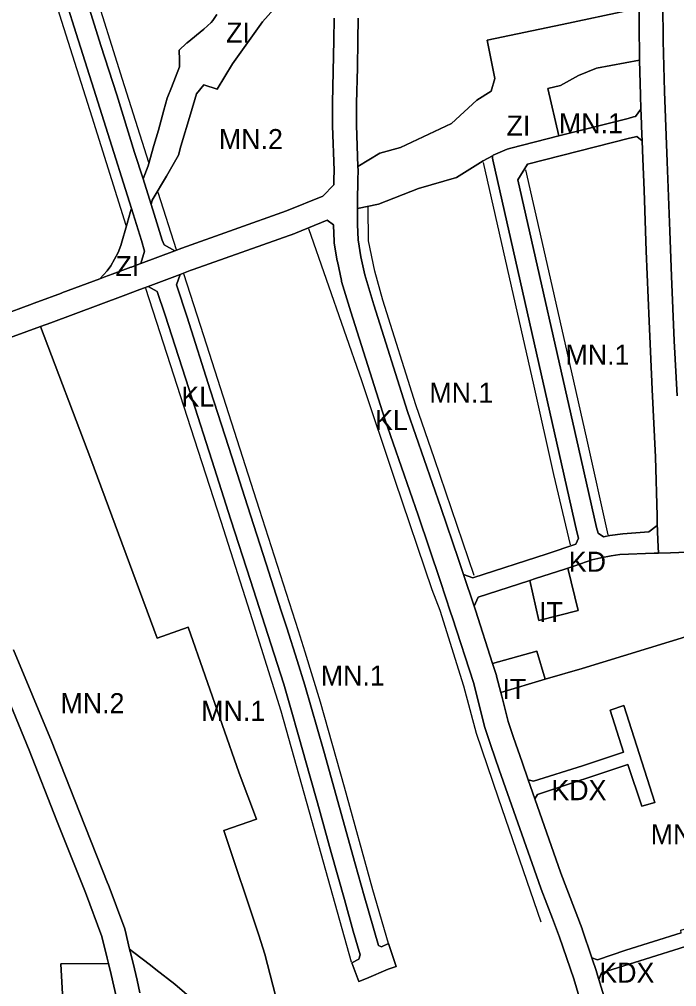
# Model space of a CAD drawing. Extents: x 7431767 to 7433133, y 5549450 to 5550702.
# Drawn here: x 7432434.9 to 7432763, y 5549892.8 to 5550375.6 of the extents above; entities that cross this region are included whole.
import ezdxf

# ---------------------------------------------------------------- set-up
doc = ezdxf.new("R2010")
doc.units = 0
for name, color, linetype in [('linie_rozgraniczajace', 7, 'Continuous'), ('nieprzekraczalne_linie_zabudowy', 7, 'Continuous'), ('oznaczenia_przeznaczen', 7, 'Continuous')]:
    doc.layers.add(name, color=color, linetype=linetype)

msp = doc.modelspace()

# ---------------------------------------------------------------- linework, layer by layer
at = {"layer": 'linie_rozgraniczajace'}
for points in [[(7432763.25, 5550187.7), (7432761.8, 5550215.11), (7432760.42, 5550247.43), (7432759.57, 5550269.96), (7432758.24, 5550304.4), (7432757.03, 5550339.63), (7432756.31, 5550364.95), (7432756.15, 5550383.55), (7432755.03, 5550391.98), (7432753.71, 5550401.33), (7432750.6, 5550417.95), (7432748.59, 5550428.19), (7432745.65, 5550438.8), (7432738.12, 5550465.56), (7432733.72, 5550481.6), (7432731.08, 5550491.16), (7432728.74, 5550502.72), (7432725.9, 5550519.48), (7432722.27, 5550540.38), (7432716.74, 5550573.19), (7432713.32, 5550592.83), (7432717.85, 5550589.96), (7432748.22, 5550570.66), (7432769.72, 5550550.02)], [(7432453.63, 5550399.36), (7432463.29, 5550368.48), (7432472.11, 5550340.78), (7432479.98, 5550315.54), (7432488.91, 5550287.48), (7432490.89, 5550281.13), (7432490.29, 5550279.68), (7432488.78, 5550273.77), (7432485.47, 5550262.65), (7432484.27, 5550259.27), (7432480.54, 5550252.54), (7432478.7, 5550250.05), (7432474.98, 5550246.08), (7432456.07, 5550239.03), (7432455.88, 5550238.96), (7432444.11, 5550234.59), (7432441.77, 5550233.72), (7432441.37, 5550233.57), (7432425.1, 5550227.62)], [(7432467.34, 5550388.9), (7432475.63, 5550362.6), (7432483.49, 5550337.84), (7432492.44, 5550309.07), (7432496.63, 5550295.93), (7432500.68, 5550283.19), (7432502.22, 5550278.43), (7432506.26, 5550265.31), (7432507.13, 5550263.14), (7432512.5, 5550260.14), (7432495.47, 5550253.73), (7432497.44, 5550259.83), (7432495.79, 5550265.14), (7432490.89, 5550281.13), (7432488.91, 5550287.48), (7432479.98, 5550315.54), (7432472.11, 5550340.78), (7432463.29, 5550368.48), (7432453.63, 5550399.36)], [(7432533.46, 5550377.98), (7432531.55, 5550375), (7432530.58, 5550374.07), (7432526.97, 5550370.61), (7432518.61, 5550363.93), (7432518.31, 5550363.66), (7432514.73, 5550360.21), (7432514.83, 5550355.38), (7432514.78, 5550351.93), (7432510.83, 5550341.51), (7432508.67, 5550336.19), (7432507.06, 5550330.24), (7432504.31, 5550320.29), (7432502.08, 5550312.68), (7432499.12, 5550302.54), (7432496.63, 5550295.93), (7432492.44, 5550309.07), (7432483.49, 5550337.84), (7432475.63, 5550362.6), (7432467.34, 5550388.9)], [(7432566.17, 5550385.73), (7432556.25, 5550374.31), (7432541.21, 5550353.36), (7432533.69, 5550340.77), (7432527.03, 5550342.86), (7432523.4, 5550338.38), (7432520.31, 5550328.19), (7432515.52, 5550312.27), (7432514.32, 5550307.76), (7432508.37, 5550297.36), (7432501.16, 5550285.34), (7432500.68, 5550283.19), (7432496.63, 5550295.93), (7432499.12, 5550302.54), (7432502.08, 5550312.68), (7432504.31, 5550320.29), (7432507.06, 5550330.24), (7432508.67, 5550336.19), (7432510.83, 5550341.51), (7432514.78, 5550351.93), (7432514.83, 5550355.38), (7432514.73, 5550360.21), (7432518.31, 5550363.66), (7432518.61, 5550363.93), (7432526.97, 5550370.61), (7432530.58, 5550374.07), (7432531.55, 5550375), (7432533.46, 5550377.98)], [(7432592.01, 5550376.26), (7432591.93, 5550365.18), (7432591.29, 5550333.96), (7432591.22, 5550322.64), (7432591.19, 5550322.5), (7432591.97, 5550300.15), (7432591.87, 5550295.66), (7432591.85, 5550293.05), (7432586.36, 5550287.41), (7432568.33, 5550280), (7432516.05, 5550261.47), (7432512.5, 5550260.14), (7432507.13, 5550263.14), (7432506.26, 5550265.31), (7432502.22, 5550278.43), (7432500.68, 5550283.19), (7432501.16, 5550285.34), (7432508.37, 5550297.36), (7432514.32, 5550307.76), (7432515.52, 5550312.27), (7432520.31, 5550328.19), (7432523.4, 5550338.38), (7432527.03, 5550342.86), (7432533.69, 5550340.77), (7432541.21, 5550353.36), (7432556.25, 5550374.31), (7432566.17, 5550385.73)], [(7432756.15, 5550383.55), (7432756.31, 5550364.95), (7432757.03, 5550339.63), (7432758.24, 5550304.4), (7432759.57, 5550269.96), (7432760.42, 5550247.43), (7432761.8, 5550215.11), (7432763.25, 5550187.7)], [(7432740.24, 5550380.4), (7432705.79, 5550373.09), (7432668.36, 5550365.21), (7432672.26, 5550346.13), (7432670.49, 5550339.82), (7432663.35, 5550335.32), (7432650.57, 5550323.57), (7432625.16, 5550311.62), (7432614.82, 5550308.86), (7432603.9, 5550302.18), (7432603.19, 5550322.78), (7432603.27, 5550333.83), (7432603.62, 5550351.4), (7432603.91, 5550365.04), (7432604.02, 5550376.25)], [(7432744.33, 5550381.26), (7432744.33, 5550372.08), (7432744.48, 5550356.8), (7432744.51, 5550355.21), (7432722.94, 5550351.17), (7432713.99, 5550347.49), (7432705.02, 5550342.58), (7432698.74, 5550341.09), (7432704.26, 5550317.38), (7432680.21, 5550311.26), (7432678.45, 5550310.88), (7432671.38, 5550307.73), (7432671.01, 5550307.53), (7432666.39, 5550304.98), (7432653.16, 5550296.61), (7432634.12, 5550291.18), (7432614.11, 5550283.37), (7432603.75, 5550281.15), (7432603.77, 5550284.42), (7432603.7, 5550284.69), (7432603.89, 5550295.47), (7432603.95, 5550300.08), (7432603.92, 5550300.23), (7432603.97, 5550300.4), (7432603.9, 5550302.18), (7432614.82, 5550308.86), (7432625.16, 5550311.62), (7432650.57, 5550323.57), (7432663.35, 5550335.32), (7432670.49, 5550339.82), (7432672.26, 5550346.13), (7432668.36, 5550365.21), (7432705.79, 5550373.09), (7432740.24, 5550380.4)], [(7432789.4, 5550110.52), (7432759.93, 5550109.32), (7432753.99, 5550109.16), (7432753.6, 5550115.69), (7432753.42, 5550120.18), (7432753.38, 5550121.22), (7432753.37, 5550122.95), (7432753.34, 5550124.42), (7432753.3, 5550127.79), (7432752.43, 5550157.07), (7432750.87, 5550190.84), (7432749.29, 5550225), (7432747.82, 5550259.82), (7432746.77, 5550290.3), (7432746.07, 5550305.96), (7432745.77, 5550314.94), (7432745.76, 5550315.29), (7432745.66, 5550317.72), (7432745.31, 5550327.88), (7432745.22, 5550330.7), (7432744.97, 5550337.75), (7432744.51, 5550355.21), (7432744.48, 5550356.8), (7432744.33, 5550372.08), (7432744.33, 5550381.26)], [(7432425.1, 5550227.62), (7432441.37, 5550233.57), (7432441.77, 5550233.72), (7432444.11, 5550234.59), (7432455.88, 5550238.96), (7432456.07, 5550239.03), (7432474.98, 5550246.08), (7432477.54, 5550247.03), (7432481.27, 5550248.42), (7432482.56, 5550248.9), (7432490.57, 5550251.89), (7432490.82, 5550251.98), (7432493.74, 5550253.08), (7432495.47, 5550253.73), (7432512.5, 5550260.14), (7432516.05, 5550261.47), (7432568.33, 5550280), (7432586.36, 5550287.41), (7432591.85, 5550293.05), (7432591.87, 5550295.66), (7432591.97, 5550300.15), (7432591.19, 5550322.5), (7432591.22, 5550322.64), (7432591.29, 5550333.96), (7432591.93, 5550365.18), (7432592.01, 5550376.26)], [(7432604.02, 5550376.25), (7432603.91, 5550365.04), (7432603.62, 5550351.4), (7432603.27, 5550333.83), (7432603.19, 5550322.78), (7432603.9, 5550302.18), (7432603.97, 5550300.4), (7432603.92, 5550300.23), (7432603.95, 5550300.08), (7432603.89, 5550295.47), (7432603.7, 5550284.69), (7432603.77, 5550284.42), (7432603.75, 5550281.15), (7432603.7, 5550273.23), (7432604.01, 5550265.55), (7432605.38, 5550257.1), (7432607.32, 5550248.01), (7432611.86, 5550233.14), (7432628.72, 5550179.83), (7432645.3, 5550132.02), (7432654.05, 5550105.97), (7432656.57, 5550098.52), (7432661.87, 5550082.72), (7432662.55, 5550080.67), (7432671.1, 5550054.07), (7432673.03, 5550048.09), (7432673.14, 5550047.76), (7432675.22, 5550039.7), (7432675.74, 5550037.75), (7432678.93, 5550025.23), (7432681.64, 5550017.1), (7432685.83, 5550004.88), (7432688.9, 5549996.13), (7432692.26, 5549986.55), (7432705.24, 5549949.47), (7432715.79, 5549921.68), (7432715.86, 5549921.49), (7432720.69, 5549907.25), (7432723, 5549900.41), (7432723.07, 5549900.28), (7432724.22, 5549896.44), (7432729.06, 5549880.57)], [(7432600.37, 5550229.61), (7432595.75, 5550244.76), (7432595.74, 5550244.99), (7432595.64, 5550245.26), (7432593.63, 5550254.74), (7432593.59, 5550254.93), (7432592.09, 5550263.99), (7432592.03, 5550264.7), (7432591.7, 5550272.89), (7432591.73, 5550273.07), (7432588.54, 5550275.33), (7432572.76, 5550268.85), (7432572.48, 5550268.74), (7432521.67, 5550250.73), (7432520.22, 5550250.22), (7432515.14, 5550248.32)], [(7432515.14, 5550248.32), (7432520.22, 5550250.22), (7432521.67, 5550250.73), (7432572.48, 5550268.74), (7432572.76, 5550268.85), (7432588.54, 5550275.33), (7432591.73, 5550273.07), (7432591.7, 5550272.89), (7432592.03, 5550264.7), (7432592.09, 5550263.99), (7432593.59, 5550254.93), (7432593.63, 5550254.74), (7432595.64, 5550245.26), (7432595.74, 5550244.99), (7432595.75, 5550244.76), (7432600.37, 5550229.61), (7432617.33, 5550176.13), (7432633.91, 5550128.17), (7432645.14, 5550095.1), (7432650.2, 5550079.8), (7432651.16, 5550076.88), (7432661.57, 5550044.58), (7432664.1, 5550034.75), (7432667.34, 5550022.05), (7432667.44, 5550021.78), (7432667.48, 5550021.63), (7432670.29, 5550013.24), (7432674.48, 5550000.98), (7432694, 5549945.31), (7432695.44, 5549941.5), (7432701.04, 5549926.81), (7432704.54, 5549917.53), (7432711.61, 5549896.7), (7432717.56, 5549877.14)], [(7432515.14, 5550248.32), (7432499.15, 5550242.3), (7432495.03, 5550240.74), (7432486.74, 5550237.65), (7432450.66, 5550224.21), (7432445.39, 5550222.28), (7432416.21, 5550211.58)], [(7432604.39, 5549895.42), (7432608.11, 5549896.97), (7432618.94, 5549901.51), (7432622.94, 5549902.96), (7432619.13, 5549914.37), (7432615.67, 5549912.7), (7432614.17, 5549913.41), (7432607.07, 5549938.19), (7432602.6, 5549954.21), (7432586.85, 5550010.29), (7432577.47, 5550043.33), (7432573.56, 5550055.63), (7432568.46, 5550071.92), (7432565.65, 5550080.33), (7432558.09, 5550103.91), (7432548.82, 5550132.73), (7432540.91, 5550157.31), (7432537.62, 5550167.54), (7432530.21, 5550190.66), (7432518.61, 5550226.88), (7432513.38, 5550243.04), (7432515.14, 5550248.32)], [(7432565.41, 5549878.06), (7432557.4, 5549908.99), (7432554.36, 5549918.48), (7432537.04, 5549970.71), (7432553.19, 5549976.48), (7432544.57, 5549999.32), (7432519.22, 5550072.32), (7432503.62, 5550066.72), (7432470.63, 5550156.04), (7432445.39, 5550222.28), (7432450.66, 5550224.21), (7432486.74, 5550237.65), (7432495.03, 5550240.74), (7432499.15, 5550242.3), (7432503.76, 5550239.85), (7432507.65, 5550227.93), (7432521.16, 5550186.18), (7432530.91, 5550155.65), (7432540.53, 5550125.84), (7432550.27, 5550095.55), (7432560.43, 5550063.85), (7432566.84, 5550043.85), (7432570.29, 5550032.2), (7432574.35, 5550017.59), (7432579.96, 5549997.98), (7432583.73, 5549984.55), (7432590.62, 5549959.74), (7432597.13, 5549936.36), (7432601.53, 5549920.51), (7432604.98, 5549908.76), (7432604.31, 5549906.61), (7432600.85, 5549904.76), (7432604.39, 5549895.42)], [(7432717.56, 5549877.14), (7432711.61, 5549896.7), (7432704.54, 5549917.53), (7432701.04, 5549926.81), (7432695.44, 5549941.5), (7432694, 5549945.31), (7432674.48, 5550000.98), (7432670.29, 5550013.24), (7432667.48, 5550021.63), (7432667.44, 5550021.78), (7432667.34, 5550022.05), (7432664.1, 5550034.75), (7432661.57, 5550044.58), (7432651.16, 5550076.88), (7432650.2, 5550079.8), (7432645.14, 5550095.1), (7432633.91, 5550128.17), (7432617.33, 5550176.13), (7432600.37, 5550229.61)], [(7432416.21, 5550211.58), (7432445.39, 5550222.28), (7432470.63, 5550156.04), (7432503.62, 5550066.72), (7432519.22, 5550072.32), (7432544.57, 5549999.32), (7432553.19, 5549976.48), (7432537.04, 5549970.71), (7432554.36, 5549918.48), (7432557.4, 5549908.99), (7432565.41, 5549878.06)], [(7432769.58, 5550068.03), (7432715.8, 5550051.66), (7432697.41, 5550046.24), (7432693.27, 5550060.35), (7432671.1, 5550054.07), (7432662.55, 5550080.67), (7432661.87, 5550082.72), (7432664, 5550087.25), (7432678.85, 5550092.09), (7432689.68, 5550095.59), (7432694.28, 5550075.57), (7432713.78, 5550080.6), (7432708.64, 5550101.64), (7432712.25, 5550102.83), (7432720.73, 5550105.84), (7432725.19, 5550106.91), (7432730.28, 5550107.86), (7432734.7, 5550108.45), (7432751.81, 5550109.11), (7432753.99, 5550109.16), (7432759.93, 5550109.32), (7432789.4, 5550110.52)], [(7432765.25, 5549919.69), (7432737.64, 5549911), (7432723.45, 5549906.26), (7432720.69, 5549907.25), (7432715.86, 5549921.49), (7432715.79, 5549921.68), (7432705.24, 5549949.47), (7432692.26, 5549986.55), (7432693.61, 5549988.74), (7432738.64, 5550003.64), (7432745.57, 5549982.94), (7432752.2, 5549984.68), (7432736.72, 5550033.1), (7432729.9, 5550030.89), (7432736.54, 5550009.9), (7432716.02, 5550003.09), (7432691.5, 5549995.38), (7432688.9, 5549996.13), (7432685.83, 5550004.88), (7432681.64, 5550017.1), (7432678.93, 5550025.23), (7432675.74, 5550037.75), (7432675.22, 5550039.7), (7432697.41, 5550046.24), (7432715.8, 5550051.66), (7432769.58, 5550068.03)], [(7432431.99, 5550060.95), (7432450.91, 5550015.4), (7432464.83, 5549979.94), (7432479.13, 5549944.19), (7432479.17, 5549944.05), (7432487.46, 5549921.7), (7432487.5, 5549921.51), (7432487.67, 5549921.05), (7432489.9, 5549911.53), (7432490.02, 5549911.05), (7432490.09, 5549910.72), (7432490.37, 5549909.95), (7432492.4, 5549901.7), (7432493.66, 5549896.09), (7432495.11, 5549889.67)], [(7432532.98, 5549876.47), (7432512.5, 5549894.02), (7432503.04, 5549901.46), (7432500.39, 5549903.5), (7432492.03, 5549909.88), (7432489.9, 5549911.53), (7432487.67, 5549921.05), (7432487.5, 5549921.51), (7432487.46, 5549921.7), (7432479.17, 5549944.05), (7432479.13, 5549944.19), (7432464.83, 5549979.94), (7432450.91, 5550015.4), (7432431.99, 5550060.95)], [(7432483.35, 5549887.26), (7432480.75, 5549898.9), (7432479.4, 5549904.39), (7432478.73, 5549907.09), (7432476.07, 5549917.85), (7432467.96, 5549939.81), (7432459.33, 5549961.38), (7432453.65, 5549975.53), (7432439.81, 5550010.85), (7432420.95, 5550056.23)], [(7432420.95, 5550056.23), (7432439.81, 5550010.85), (7432453.65, 5549975.53), (7432459.33, 5549961.38), (7432467.96, 5549939.81), (7432476.07, 5549917.85), (7432478.73, 5549907.09), (7432479.4, 5549904.39), (7432455.58, 5549904.25), (7432457.52, 5549868.02)], [(7432495.11, 5549889.67), (7432493.66, 5549896.09), (7432492.4, 5549901.7), (7432490.37, 5549909.95), (7432490.09, 5549910.72), (7432490.02, 5549911.05), (7432489.9, 5549911.53), (7432492.03, 5549909.88), (7432500.39, 5549903.5), (7432503.04, 5549901.46), (7432512.5, 5549894.02), (7432532.98, 5549876.47)], [(7432729.06, 5549880.57), (7432724.22, 5549896.44), (7432725.53, 5549899.73), (7432747.33, 5549906.59), (7432767.43, 5549912.84)]]:
    msp.add_lwpolyline(points, dxfattribs=at)
for points in [[(7432744.51, 5550355.21), (7432744.97, 5550337.75), (7432745.22, 5550330.7), (7432742.4, 5550327.12), (7432741.44, 5550326.87), (7432738.78, 5550326.18), (7432704.26, 5550317.38), (7432698.74, 5550341.09), (7432705.02, 5550342.58), (7432713.99, 5550347.49), (7432722.94, 5550351.17)], [(7432745.22, 5550330.7), (7432745.31, 5550327.88), (7432745.66, 5550317.72), (7432745.76, 5550315.29), (7432745.77, 5550314.94), (7432743.11, 5550317.16), (7432741.78, 5550316.87), (7432739.49, 5550316.36), (7432688.6, 5550303.35), (7432683.76, 5550295.45), (7432714.2, 5550161.12), (7432722.98, 5550121.94), (7432723.85, 5550119.16), (7432726.49, 5550117.33), (7432729.65, 5550117.94), (7432736.22, 5550118.77), (7432749.09, 5550119.76), (7432753.37, 5550122.95), (7432753.38, 5550121.22), (7432753.42, 5550120.18), (7432753.6, 5550115.69), (7432753.99, 5550109.16), (7432751.81, 5550109.11), (7432734.7, 5550108.45), (7432730.28, 5550107.86), (7432725.19, 5550106.91), (7432720.73, 5550105.84), (7432712.25, 5550102.83), (7432708.64, 5550101.64), (7432707.13, 5550101.14), (7432692.52, 5550096.5), (7432689.68, 5550095.59), (7432678.85, 5550092.09), (7432664, 5550087.25), (7432661.87, 5550082.72), (7432656.57, 5550098.52), (7432661.23, 5550096.89), (7432698.37, 5550108.84), (7432712.75, 5550113.66), (7432713.94, 5550116.63), (7432713.22, 5550119.9), (7432704.44, 5550158.93), (7432671.29, 5550305.44), (7432671.16, 5550306.34), (7432671.01, 5550307.53), (7432671.38, 5550307.73), (7432678.45, 5550310.88), (7432680.21, 5550311.26), (7432704.26, 5550317.38), (7432738.78, 5550326.18), (7432741.44, 5550326.87), (7432742.4, 5550327.12)], [(7432753.37, 5550122.95), (7432749.09, 5550119.76), (7432736.22, 5550118.77), (7432729.65, 5550117.94), (7432726.49, 5550117.33), (7432723.85, 5550119.16), (7432722.98, 5550121.94), (7432714.2, 5550161.12), (7432683.76, 5550295.45), (7432688.6, 5550303.35), (7432739.49, 5550316.36), (7432741.78, 5550316.87), (7432743.11, 5550317.16), (7432745.77, 5550314.94), (7432746.07, 5550305.96), (7432746.77, 5550290.3), (7432747.82, 5550259.82), (7432749.29, 5550225), (7432750.87, 5550190.84), (7432752.43, 5550157.07), (7432753.3, 5550127.79), (7432753.34, 5550124.42)], [(7432671.01, 5550307.53), (7432671.16, 5550306.34), (7432671.29, 5550305.44), (7432704.44, 5550158.93), (7432713.22, 5550119.9), (7432713.94, 5550116.63), (7432712.75, 5550113.66), (7432698.37, 5550108.84), (7432661.23, 5550096.89), (7432656.57, 5550098.52), (7432654.05, 5550105.97), (7432645.3, 5550132.02), (7432628.72, 5550179.83), (7432611.86, 5550233.14), (7432607.32, 5550248.01), (7432605.38, 5550257.1), (7432604.01, 5550265.55), (7432603.7, 5550273.23), (7432603.75, 5550281.15), (7432614.11, 5550283.37), (7432634.12, 5550291.18), (7432653.16, 5550296.61), (7432666.39, 5550304.98)], [(7432490.89, 5550281.13), (7432495.79, 5550265.14), (7432497.44, 5550259.83), (7432495.47, 5550253.73), (7432493.74, 5550253.08), (7432490.82, 5550251.98), (7432490.57, 5550251.89), (7432482.56, 5550248.9), (7432481.27, 5550248.42), (7432477.54, 5550247.03), (7432474.98, 5550246.08), (7432478.7, 5550250.05), (7432480.54, 5550252.54), (7432484.27, 5550259.27), (7432485.47, 5550262.65), (7432488.78, 5550273.77), (7432490.29, 5550279.68)], [(7432515.14, 5550248.32), (7432513.38, 5550243.04), (7432518.61, 5550226.88), (7432530.21, 5550190.66), (7432537.62, 5550167.54), (7432540.91, 5550157.31), (7432548.82, 5550132.73), (7432558.09, 5550103.91), (7432565.65, 5550080.33), (7432568.46, 5550071.92), (7432573.56, 5550055.63), (7432577.47, 5550043.33), (7432586.85, 5550010.29), (7432602.6, 5549954.21), (7432607.07, 5549938.19), (7432614.17, 5549913.41), (7432615.67, 5549912.7), (7432619.13, 5549914.37), (7432622.94, 5549902.96), (7432618.94, 5549901.51), (7432608.11, 5549896.97), (7432604.39, 5549895.42), (7432600.85, 5549904.76), (7432604.31, 5549906.61), (7432604.98, 5549908.76), (7432601.53, 5549920.51), (7432597.13, 5549936.36), (7432590.62, 5549959.74), (7432583.73, 5549984.55), (7432579.96, 5549997.98), (7432574.35, 5550017.59), (7432570.29, 5550032.2), (7432566.84, 5550043.85), (7432560.43, 5550063.85), (7432550.27, 5550095.55), (7432540.53, 5550125.84), (7432530.91, 5550155.65), (7432521.16, 5550186.18), (7432507.65, 5550227.93), (7432503.76, 5550239.85), (7432499.15, 5550242.3)], [(7432708.64, 5550101.64), (7432713.78, 5550080.6), (7432694.28, 5550075.57), (7432689.68, 5550095.59), (7432692.52, 5550096.5), (7432707.13, 5550101.14)], [(7432671.1, 5550054.07), (7432693.27, 5550060.35), (7432697.41, 5550046.24), (7432675.22, 5550039.7), (7432673.14, 5550047.76), (7432673.03, 5550048.09)], [(7432688.9, 5549996.13), (7432691.5, 5549995.38), (7432716.02, 5550003.09), (7432736.54, 5550009.9), (7432729.9, 5550030.89), (7432736.72, 5550033.1), (7432752.2, 5549984.68), (7432745.57, 5549982.94), (7432738.64, 5550003.64), (7432693.61, 5549988.74), (7432692.26, 5549986.55)], [(7432720.69, 5549907.25), (7432723.45, 5549906.26), (7432737.64, 5549911), (7432765.25, 5549919.69), (7432765.07, 5549920.96), (7432788.58, 5549928.21), (7432791.4, 5549918.72), (7432767.8, 5549911.58), (7432767.43, 5549912.84), (7432747.33, 5549906.59), (7432725.53, 5549899.73), (7432724.22, 5549896.44), (7432723.07, 5549900.28), (7432723, 5549900.41)], [(7432457.52, 5549868.02), (7432455.58, 5549904.25), (7432479.4, 5549904.39), (7432480.75, 5549898.9), (7432483.35, 5549887.26), (7432485.17, 5549874.8), (7432485.5, 5549872.15)]]:
    msp.add_lwpolyline(points, close=True, dxfattribs=at)
at = {"layer": 'nieprzekraczalne_linie_zabudowy'}
for points in [[(7432440.26, 5550491.62), (7432456.76, 5550439.26), (7432471.07, 5550394.23), (7432486.2, 5550345.79), (7432499.33, 5550304.33)], [(7432488.21, 5550272.75), (7432471.21, 5550326.79), (7432456.11, 5550374.54), (7432441.18, 5550422.29), (7432421.07, 5550485.33)], [(7432666.39, 5550304.11), (7432682.33, 5550233.68), (7432691.65, 5550192.58), (7432701.62, 5550148.41), (7432709.84, 5550113.28)], [(7432728.91, 5550118.36), (7432718.39, 5550165.61), (7432708.46, 5550208.92), (7432698.46, 5550253.78), (7432687.7, 5550300.5)], [(7432504.06, 5550289.38), (7432513.15, 5550260.66)], [(7432661.93, 5550098.09), (7432642.18, 5550156.32), (7432632.83, 5550183.13), (7432616.42, 5550235.48), (7432612.31, 5550249.94), (7432609.11, 5550265.13), (7432608.95, 5550281.82)], [(7432695.39, 5549925.07), (7432674.06, 5549986.91), (7432663.02, 5550019.25), (7432656.8, 5550042.83), (7432644.93, 5550080.56), (7432640.98, 5550090.88), (7432622.56, 5550145.48), (7432605.83, 5550195.23), (7432579.35, 5550271.09)], [(7432516.9, 5550248.76), (7432526.76, 5550217.84), (7432554.54, 5550131.19), (7432574.09, 5550070.51), (7432577.4, 5550059.94), (7432585.08, 5550035.01), (7432596.97, 5549992.55), (7432611.23, 5549941.24), (7432619.06, 5549914.48)], [(7432600.7, 5549905), (7432579.78, 5549979.92), (7432565.6, 5550030.29), (7432551.27, 5550075.83), (7432535.6, 5550124.93), (7432520.54, 5550171.65), (7432505.1, 5550219.22), (7432498.09, 5550241.31)]]:
    msp.add_lwpolyline(points, dxfattribs=at)

# ---------------------------------------------------------------- texts
at = {"layer": 'oznaczenia_przeznaczen'}
for s, p in [('ZI', (7432538.07, 5550364.02)), ('ZI', (7432678.11, 5550317.55)), ('MN.1', (7432704.25, 5550318.75)), ('MN.2', (7432534.51, 5550310.83)), ('ZI', (7432482.82, 5550247.45)), ('MN.1', (7432707.5, 5550203.22)), ('MN.1', (7432639.56, 5550184.23)), ('KL', (7432515.77, 5550182.35)), ('KL', (7432612.48, 5550170.59)), ('KD', (7432709.17, 5550099.92)), ('IT', (7432694.32, 5550074.81)), ('MN.1', (7432585.35, 5550043.11)), ('IT', (7432676.04, 5550036.46)), ('MN.2', (7432455.41, 5550029.31)), ('MN.1', (7432525.66, 5550025.49)), ('KDX', (7432700.49, 5549985.9)), ('MN.1', (7432750.07, 5549963.9)), ('KDX', (7432724.41, 5549894.82))]:
    msp.add_text(s, height=10, dxfattribs=at).set_placement(p)

doc.saveas('drawing.dxf')
